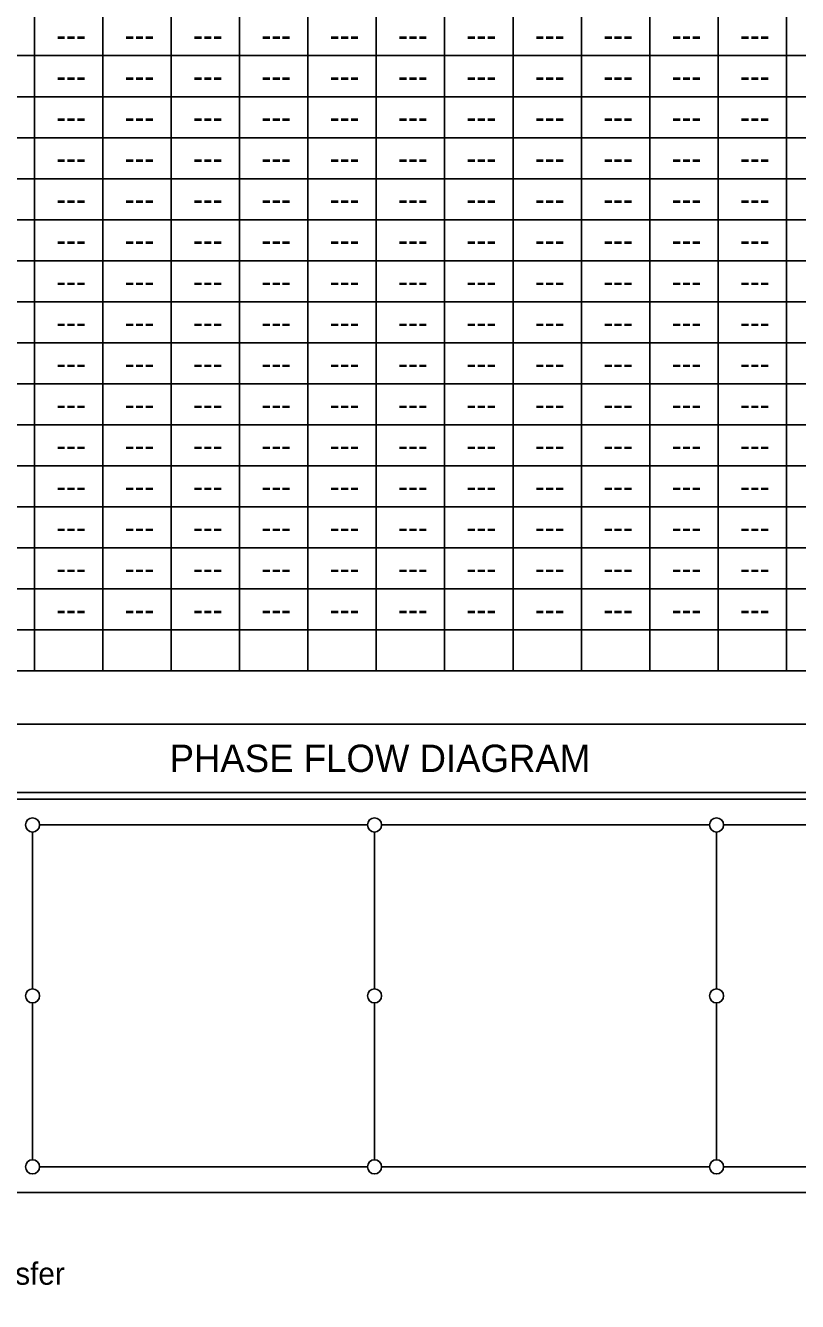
# Model space of a CAD drawing. Extents: x 10040 to 81668, y 7194 to 11018.
# Drawn here: x 11479 to 11931, y 8516 to 9263 of the extents above; entities that cross this region are included whole.
import ezdxf

# ---------------------------------------------------------------- set-up
doc = ezdxf.new("R2010")
doc.units = 0
for name, color, linetype in [('dsnStdTable', 7, 'Continuous'), ('Level 4', 7, 'Continuous'), ('wetSpecialNote', 7, 'Continuous')]:
    doc.layers.add(name, color=color, linetype=linetype)

msp = doc.modelspace()

# ---------------------------------------------------------------- linework, layer by layer
at = {"layer": 'Level 4'}
for p, q in [((11524.49, 9889.02), (11524.49, 8884.97)), ((11524.49, 9889.02), (11524.49, 8884.97)), ((11724.49, 9889.02), (11724.49, 8884.97)), ((11724.49, 9889.02), (11724.49, 8884.97)), ((11924.49, 9889.02), (11924.49, 8884.97)), ((11924.49, 9889.02), (11924.49, 8884.97)), ((11564.49, 9665.02), (11564.49, 8884.97)), ((11764.49, 9665.02), (11764.49, 8884.97)), ((11484.49, 9641.02), (11484.49, 8884.97)), ((11604.49, 9641.02), (11604.49, 8884.97)), ((11644.49, 9641.02), (11644.49, 8884.97)), ((11684.49, 9641.02), (11684.49, 8884.97)), ((11804.49, 9641.02), (11804.49, 8884.97)), ((11844.49, 9641.02), (11844.49, 8884.97)), ((11884.49, 9641.02), (11884.49, 8884.97)), ((12518.28, 8809.82), (10868.28, 8809.82)), ((11483.44, 8790.69), (11483.44, 8698.92)), ((11487.57, 8794.82), (11679.37, 8794.82)), ((11683.5, 8790.69), (11683.5, 8698.92)), ((11687.62, 8794.82), (11879.42, 8794.82)), ((11883.55, 8790.69), (11883.55, 8698.92)), ((11887.68, 8794.82), (12079.47, 8794.82)), ((11483.44, 8690.67), (11483.44, 8598.9)), ((11683.5, 8690.67), (11683.5, 8598.9)), ((11883.55, 8690.67), (11883.55, 8598.9)), ((11487.57, 8594.77), (11679.37, 8594.77)), ((11687.62, 8594.77), (11879.42, 8594.77)), ((11887.68, 8594.77), (12079.47, 8594.77)), ((12518.28, 8579.77), (10868.28, 8579.77))]:
    msp.add_line(p, q, dxfattribs=at)
for points in [[(10664.49, 9929.02), (12524.49, 9929.02), (12524.49, 8884.97), (10664.49, 8884.97)], [(10868.28, 8853.82), (12518.28, 8853.82), (12518.28, 8503.82), (10868.28, 8503.82)]]:
    msp.add_lwpolyline(points, close=True, dxfattribs=at)
msp.add_lwpolyline([(12518.28, 8813.82), (10868.28, 8813.82)], dxfattribs=at)
for centre in [(11483.44, 8794.82), (11683.5, 8794.82), (11883.55, 8794.82), (11483.44, 8694.79), (11683.5, 8694.79), (11883.55, 8694.79), (11483.44, 8594.77), (11683.5, 8594.77), (11883.55, 8594.77)]:
    msp.add_circle(centre, 4.13, dxfattribs=at)
at = {"layer": 'wetSpecialNote'}
for p, q in [((12524.49, 9244.98), (10664.49, 9244.98)), ((10824.49, 9220.98), (12524.49, 9220.98)), ((12524.49, 9196.98), (10824.49, 9196.98)), ((10824.49, 9172.98), (12524.49, 9172.98)), ((12524.49, 9148.98), (10824.49, 9148.98)), ((10664.49, 9124.98), (12524.49, 9124.98)), ((10824.49, 9100.97), (12524.49, 9100.97)), ((10824.49, 9076.97), (12524.49, 9076.97)), ((10824.49, 9052.97), (12524.49, 9052.97)), ((10824.49, 9028.97), (12524.49, 9028.97)), ((10664.49, 9004.97), (12524.49, 9004.97)), ((10824.49, 8980.97), (12524.49, 8980.97)), ((10824.49, 8956.97), (12524.49, 8956.97)), ((10824.49, 8932.97), (12524.49, 8932.97)), ((10824.49, 8908.96), (12524.49, 8908.96))]:
    msp.add_line(p, q, dxfattribs=at)

# ---------------------------------------------------------------- texts
at = {"layer": 'dsnStdTable'}
for p in [(11497.28, 9250.48), (11537.28, 9250.48), (11577.28, 9250.48), (11617.28, 9250.48), (11657.28, 9250.48), (11697.28, 9250.48), (11737.28, 9250.48), (11777.28, 9250.48), (11817.28, 9250.48), (11857.28, 9250.48), (11897.28, 9250.48), (11497.28, 9226.48), (11537.28, 9226.48), (11577.28, 9226.48), (11617.28, 9226.48), (11657.28, 9226.48), (11697.28, 9226.48), (11737.28, 9226.48), (11777.28, 9226.48), (11817.28, 9226.48), (11857.28, 9226.48), (11897.28, 9226.48), (11497.28, 9202.48), (11537.28, 9202.48), (11577.28, 9202.48), (11617.28, 9202.48), (11657.28, 9202.48), (11697.28, 9202.48), (11737.28, 9202.48), (11777.28, 9202.48), (11817.28, 9202.48), (11857.28, 9202.48), (11897.28, 9202.48), (11497.28, 9178.48), (11537.28, 9178.48), (11577.28, 9178.48), (11617.28, 9178.48), (11657.28, 9178.48), (11697.28, 9178.48), (11737.28, 9178.48), (11777.28, 9178.48), (11817.28, 9178.48), (11857.28, 9178.48), (11897.28, 9178.48), (11497.28, 9154.48), (11537.28, 9154.48), (11577.28, 9154.48), (11617.28, 9154.48), (11657.28, 9154.48), (11697.28, 9154.48), (11737.28, 9154.48), (11777.28, 9154.48), (11817.28, 9154.48), (11857.28, 9154.48), (11897.28, 9154.48), (11497.28, 9130.48), (11537.28, 9130.48), (11577.28, 9130.48), (11617.28, 9130.48), (11657.28, 9130.48), (11697.28, 9130.48), (11737.28, 9130.48), (11777.28, 9130.48), (11817.28, 9130.48), (11857.28, 9130.48), (11897.28, 9130.48), (11497.28, 9106.48), (11537.28, 9106.48), (11577.28, 9106.48), (11617.28, 9106.48), (11657.28, 9106.48), (11697.28, 9106.48), (11737.28, 9106.48), (11777.28, 9106.48), (11817.28, 9106.48), (11857.28, 9106.48), (11897.28, 9106.48), (11497.28, 9082.47), (11537.28, 9082.47), (11577.28, 9082.47), (11617.28, 9082.47), (11657.28, 9082.47), (11697.28, 9082.47), (11737.28, 9082.47), (11777.28, 9082.47), (11817.28, 9082.47), (11857.28, 9082.47), (11897.28, 9082.47), (11497.28, 9058.47), (11537.28, 9058.47), (11577.28, 9058.47), (11617.28, 9058.47), (11657.28, 9058.47), (11697.28, 9058.47), (11737.28, 9058.47), (11777.28, 9058.47), (11817.28, 9058.47), (11857.28, 9058.47), (11897.28, 9058.47), (11497.28, 9034.47), (11537.28, 9034.47), (11577.28, 9034.47), (11617.28, 9034.47), (11657.28, 9034.47), (11697.28, 9034.47), (11737.28, 9034.47), (11777.28, 9034.47), (11817.28, 9034.47), (11857.28, 9034.47), (11897.28, 9034.47), (11497.28, 9010.47), (11537.28, 9010.47), (11577.28, 9010.47), (11617.28, 9010.47), (11657.28, 9010.47), (11697.28, 9010.47), (11737.28, 9010.47), (11777.28, 9010.47), (11817.28, 9010.47), (11857.28, 9010.47), (11897.28, 9010.47), (11497.28, 8986.47), (11537.28, 8986.47), (11577.28, 8986.47), (11617.28, 8986.47), (11657.28, 8986.47), (11697.28, 8986.47), (11737.28, 8986.47), (11777.28, 8986.47), (11817.28, 8986.47), (11857.28, 8986.47), (11897.28, 8986.47), (11497.28, 8962.47), (11537.28, 8962.47), (11577.28, 8962.47), (11617.28, 8962.47), (11657.28, 8962.47), (11697.28, 8962.47), (11737.28, 8962.47), (11777.28, 8962.47), (11817.28, 8962.47), (11857.28, 8962.47), (11897.28, 8962.47), (11497.28, 8938.47), (11537.28, 8938.47), (11577.28, 8938.47), (11617.28, 8938.47), (11657.28, 8938.47), (11697.28, 8938.47), (11737.28, 8938.47), (11777.28, 8938.47), (11817.28, 8938.47), (11857.28, 8938.47), (11897.28, 8938.47), (11497.28, 8914.46), (11537.28, 8914.46), (11577.28, 8914.46), (11617.28, 8914.46), (11657.28, 8914.46), (11697.28, 8914.46), (11737.28, 8914.46), (11777.28, 8914.46), (11817.28, 8914.46), (11857.28, 8914.46), (11897.28, 8914.46)]:
    msp.add_text('---', height=13, dxfattribs=at).set_placement(p)
at = {"layer": 'Level 4'}
for s, height, p in [('PHASE FLOW DIAGRAM', 16, (11563.58, 8825.82)), ('Flow path when phase is not requested before right of way transfer', 13, (10988.19, 8525.79))]:
    msp.add_text(s, height=height, dxfattribs=at).set_placement(p)

doc.saveas('drawing.dxf')
